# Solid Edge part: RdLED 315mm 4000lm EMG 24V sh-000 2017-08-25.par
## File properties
Author: lukasz.lemanski
Template: iso metric part.par
Last saved by: lukasz.lemanski
Revision: 1
Application: Solid Edge
Username: lukasz.lemanski
Gęstość: 0,000 kg/m^3
Dokładność: 0,990
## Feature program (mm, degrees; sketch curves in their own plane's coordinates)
body "unnamed Body 1"
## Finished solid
Body 1: solid body, 3078 faces, 7968 edges, 5186 vertices, 3 separate solids.
  Faces by surface: plane 2555, cylinder 237, spline 160, cone 52, torus 22, sphere 20, swept 18, spun 14
  Edges by curve: line 6836, curve on surface 600, circle 312, ellipse 132, spline 76, intersection 12
Bounding box of the edges (mm; curved faces can reach further): 311.800 x 4.500 x 311.800, from (-155.9, -3.5, -155.9) to (155.9, 1, 155.9).
Cylindrical faces by radius (mm): R0.2 x78, R0.2002 x4, R0.2169 x6, R0.25 x24, R0.3 x4, R0.3373 x6, R0.4 x16, R0.4006 x4, R0.4008 x4, R0.525 x4, R0.6 x24, R0.75 x5, R1 x14, R1.0894 x4, R1.1 x28, R2.15 x8, R157.5 x4
Conical faces (half-angle, radius in mm at the cone's reference point): 0.5 deg R0.5056 x8, 0.5 deg R1.0082 x8, 1 deg R0.5511 x4, 10 deg R0.2132 x4, 10 deg R0.4132 x4, 18.4844 deg R1.0657 x8, 27.363 deg R0.6214 x4, 45 deg R0.575 x4, 45 deg R0.625 x8
Toroidal faces (ring radius, tube radius in mm): R0.1 r0.2 x2, R0.8 r0.2 x8, R0.8522 r0.3 x4, R0.9002 r0.2 x2, R0.9018 r0.2 x2, R1.3 r0.2 x4
Spherical faces by radius (mm): R0.2 x16, R0.6 x4
Planar faces by outward normal: +x 63, +y 23, +z 63, -x 63, -y 460, -z 83, oblique 1800
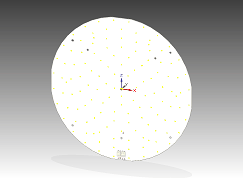
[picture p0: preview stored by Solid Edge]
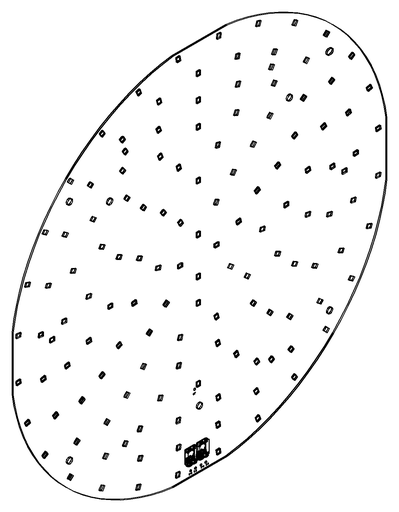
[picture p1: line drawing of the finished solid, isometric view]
